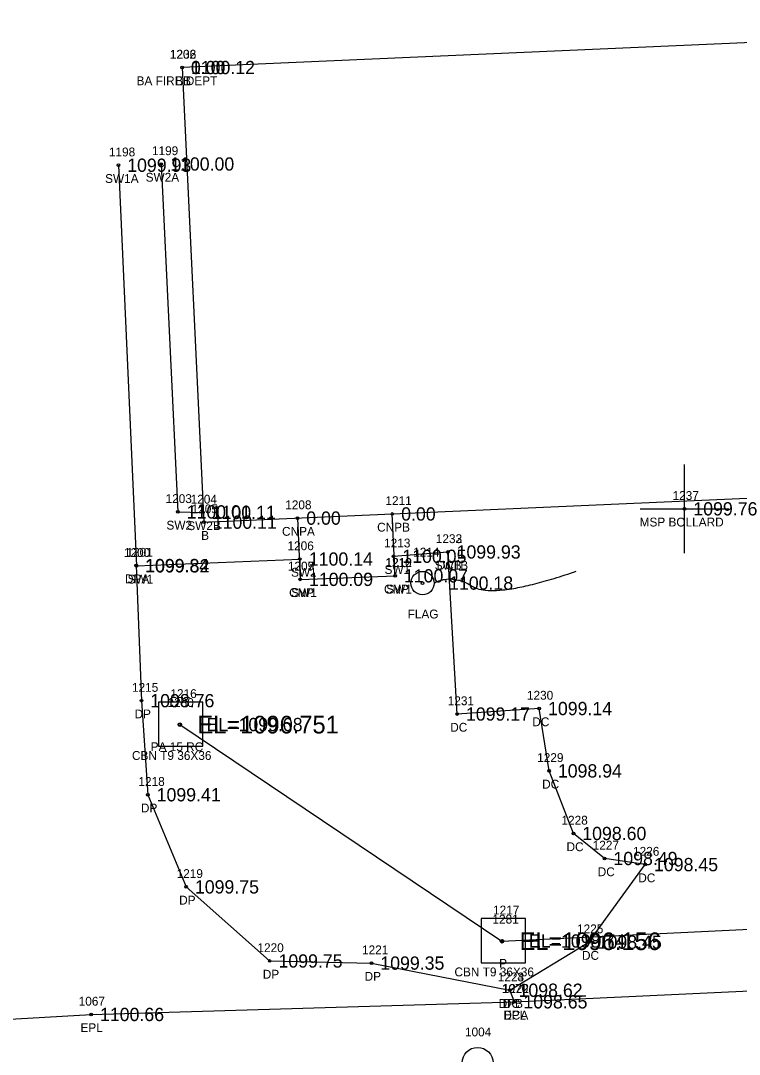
# Model space of a CAD drawing. Extents: x 1539151 to 1541799, y 1198646 to 1201165.
# Drawn here: x 1539498.1 to 1539579.5, y 1199362.1 to 1199479 of the extents above; entities that cross this region are included whole.
import ezdxf

# ---------------------------------------------------------------- set-up
doc = ezdxf.new("R2010")
doc.units = 0
for name, color, linetype in [('RD_EX_Bldg', 7, 'Continuous'), ('RD_EX_Bldg_txCode', 7, 'Continuous'), ('RD_EX_BldgApp', 7, 'Continuous'), ('RD_EX_BldgApp_txCode', 7, 'Continuous'), ('RD_EX_Conc', 7, 'Continuous'), ('RD_EX_Conc_txCode', 7, 'Continuous'), ('RD_EX_DR_Inlet', 7, 'Continuous'), ('RD_EX_DR_Inlet_txCode', 7, 'Continuous'), ('RD_EX_DR_Pipe', 7, 'Continuous'), ('RD_EX_DR_Pipe_txCode', 7, 'Continuous'), ('RD_EX_Driveway', 7, 'Continuous'), ('RD_EX_Driveway_txCode', 7, 'Continuous'), ('RD_EX_DV_Prop_txCode', 7, 'Continuous'), ('RD_EX_DV_PropPin', 7, 'Continuous'), ('RD_EX_Misc', 7, 'Continuous'), ('RD_EX_Misc_txCode', 7, 'Continuous'), ('RD_EX_Road', 7, 'Continuous'), ('RD_EX_Road_txCode', 7, 'Continuous'), ('RD_EX_SU_Telecom', 7, 'Continuous'), ('RD_EX_TX_Bldg_ELEV', 7, 'Continuous'), ('RD_EX_TX_BldgApp_ELEV', 7, 'Continuous'), ('RD_EX_TX_Conc_ELEV', 7, 'Continuous'), ('RD_EX_TX_DR_Inlet_ELEV', 7, 'Continuous'), ('RD_EX_TX_Driveway_ELEV', 7, 'Continuous'), ('RD_EX_TX_Misc_ELEV', 7, 'Continuous'), ('RD_EX_TX_Road_ELEV', 7, 'Continuous'), ('RD_SMD_Locator', 7, 'Continuous'), ('RD_TX_Pipe_ElevEX', 7, 'Continuous')]:
    doc.layers.add(name, color=color, linetype=linetype)

msp = doc.modelspace()

# ---------------------------------------------------------------- linework, layer by layer
at = {"layer": 'RD_EX_Bldg'}
msp.add_lwpolyline([(1539516.41, 1199473.69), (1539518.88, 1199422.27), (1539639.27, 1199427.57), (1539636.8, 1199478.99), (1539516.41, 1199473.69)], dxfattribs=at)
at = {"layer": 'RD_EX_BldgApp'}
msp.add_lwpolyline([(1539529.46, 1199422.73), (1539529.77, 1199415.8), (1539540.51, 1199416.2), (1539540.2, 1199423.2)], dxfattribs=at)
at = {"layer": 'RD_EX_Conc'}
for points in [[(1539509.2, 1199462.64), (1539511.25, 1199417.33), (1539529.75, 1199418.1), (1539529.77, 1199415.8), (1539540.51, 1199416.2), (1539540.33, 1199418.41), (1539546.47, 1199418.9)], [(1539514.06, 1199462.78), (1539515.93, 1199423.43), (1539518.76, 1199423.37)], [(1539554.03, 1199368.02), (1539553.48, 1199369.33), (1539562.44, 1199374.77), (1539568.81, 1199383.54), (1539564.22, 1199384.23), (1539560.69, 1199387.06), (1539557.93, 1199394.14), (1539556.82, 1199401.19), (1539547.53, 1199400.57), (1539546.47, 1199418.9)]]:
    msp.add_lwpolyline(points, dxfattribs=at)
at = {"layer": 'RD_EX_DR_Inlet'}
for p, q in [((1539518.76, 1199396.93), (1539518.76, 1199401.93)), ((1539555.25, 1199372.44), (1539555.25, 1199377.44))]:
    msp.add_line(p, q, dxfattribs=at)
for points in [[(1539518.76, 1199396.93), (1539518.76, 1199401.93), (1539513.76, 1199401.93), (1539513.76, 1199396.93)], [(1539555.25, 1199372.44), (1539555.25, 1199377.44), (1539550.25, 1199377.44), (1539550.25, 1199372.44)]]:
    msp.add_lwpolyline(points, close=True, dxfattribs=at)
at = {"layer": 'RD_EX_DR_Pipe'}
msp.add_lwpolyline([(1539516.15, 1199399.37), (1539552.6, 1199374.87), (1539649.98, 1199379.6)], dxfattribs=at)
at = {"layer": 'RD_EX_Driveway'}
msp.add_lwpolyline([(1539511.22, 1199417.36), (1539511.81, 1199402.08), (1539512.53, 1199391.44), (1539516.86, 1199381.02), (1539526.32, 1199372.64), (1539537.84, 1199372.4), (1539553.48, 1199369.33)], dxfattribs=at)
at = {"layer": 'RD_EX_DV_PropPin'}
msp.add_circle((1539549.85, 1199361.11), 1.75, dxfattribs=at)
at = {"layer": 'RD_EX_Misc'}
for p, q in [((1539573.26, 1199418.78), (1539573.26, 1199428.78)), ((1539568.26, 1199423.78), (1539578.26, 1199423.78))]:
    msp.add_line(p, q, dxfattribs=at)
at = {"layer": 'RD_EX_Road'}
msp.add_lwpolyline([(1539428.76, 1199454.93), (1539416.46, 1199395.23), (1539420.91, 1199377.84), (1539428.29, 1199368.53), (1539440.24, 1199363.06), (1539462.84, 1199364.11), (1539506.12, 1199366.59), (1539554.03, 1199368.02), (1539606.53, 1199370.48), (1539651.89, 1199372.76), (1539672.94, 1199372.91), (1539707.02, 1199374.85), (1539748.7, 1199377.62), (1539769.05, 1199378.19), (1539812.94, 1199380.16), (1539830.48, 1199381.23), (1539857.01, 1199382.87), (1539908.22, 1199385.45), (1539955.82, 1199389.74), (1539996.13, 1199397.4), (1540037.85, 1199410.51), (1540050.26, 1199415.61), (1540093.12, 1199444.78)], dxfattribs=at)
at = {"layer": 'RD_EX_SU_Telecom'}
msp.add_circle((1539543.62, 1199415.38), 1.32, dxfattribs=at)
msp.add_open_spline([(1539544.94, 1199415.38), (1539546.95, 1199416.48), (1539551.63, 1199413.53), (1539561, 1199416.71)], degree=2, dxfattribs=at)
at = {"layer": 'RD_SMD_Locator'}
for centre, radius in [((1539516.41, 1199473.69), 0.15), ((1539516.41, 1199473.69), 0.15), ((1539509.2, 1199462.64), 0.15), ((1539514.06, 1199462.78), 0.15), ((1539515.93, 1199423.43), 0.15), ((1539518.76, 1199423.37), 0.15), ((1539540.2, 1199423.2), 0.15), ((1539573.26, 1199423.78), 0.15), ((1539518.88, 1199422.27), 0.15), ((1539529.46, 1199422.73), 0.15), ((1539540.33, 1199418.41), 0.15), ((1539546.47, 1199418.9), 0.15), ((1539546.47, 1199418.9), 0.15), ((1539511.22, 1199417.36), 0.15), ((1539511.25, 1199417.33), 0.15), ((1539529.75, 1199418.1), 0.15), ((1539540.51, 1199416.2), 0.15), ((1539540.51, 1199416.2), 0.15), ((1539529.77, 1199415.8), 0.15), ((1539529.77, 1199415.8), 0.15), ((1539543.62, 1199415.38), 0.15), ((1539511.81, 1199402.08), 0.15), ((1539556.82, 1199401.19), 0.15), ((1539547.53, 1199400.57), 0.15), ((1539516.15, 1199399.37), 0.2), ((1539516.17, 1199399.38), 0.15), ((1539557.93, 1199394.14), 0.15), ((1539512.53, 1199391.44), 0.15), ((1539560.69, 1199387.06), 0.15), ((1539564.22, 1199384.23), 0.15), ((1539568.81, 1199383.54), 0.15), ((1539516.86, 1199381.02), 0.15), ((1539552.6, 1199374.87), 0.2), ((1539552.66, 1199374.9), 0.15), ((1539562.44, 1199374.77), 0.15), ((1539526.32, 1199372.64), 0.15), ((1539537.84, 1199372.4), 0.15), ((1539553.48, 1199369.33), 0.15), ((1539553.48, 1199369.33), 0.15), ((1539554.03, 1199368.02), 0.15), ((1539554.03, 1199368.02), 0.15), ((1539506.12, 1199366.59), 0.15)]:
    msp.add_circle(centre, radius, dxfattribs=at)

# ---------------------------------------------------------------- texts
at = {"layer": 'RD_EX_Bldg_txCode'}
for s, p in [('1202', (1539515.02, 1199474.69)), ('1236', (1539515.04, 1199474.69)), ('BA FIRE DEPT', (1539511.26, 1199471.69)), ('BB', (1539515.63, 1199471.69)), ('1205', (1539517.49, 1199423.27)), ('B', (1539518.57, 1199420.27))]:
    msp.add_text(s, height=1, dxfattribs=at).set_placement(p)
at = {"layer": 'RD_EX_BldgApp_txCode'}
for s, p in [('1208', (1539528.08, 1199423.73)), ('1211', (1539539.42, 1199424.2)), ('CNPB', (1539538.48, 1199421.2)), ('CNPA', (1539527.72, 1199420.73)), ('1214', (1539542.56, 1199418.38)), ('1209', (1539528.38, 1199416.8)), ('1210', (1539539.41, 1199417.2)), ('CNP', (1539539.26, 1199414.2)), ('CNP', (1539528.52, 1199413.8)), ('FLAG', (1539541.93, 1199411.38))]:
    msp.add_text(s, height=1, dxfattribs=at).set_placement(p)
at = {"layer": 'RD_EX_Conc_txCode'}
for s, p in [('1198', (1539508.13, 1199463.64)), ('1199', (1539513, 1199463.78)), ('SW2A', (1539512.29, 1199460.78)), ('SW1A', (1539507.7, 1199460.64)), ('1203', (1539514.54, 1199424.43)), ('1204', (1539517.38, 1199424.37)), ('SW2', (1539514.64, 1199421.43)), ('SW2B', (1539517, 1199421.37)), ('1232', (1539545.12, 1199419.9)), ('1233', (1539545.12, 1199419.9)), ('1206', (1539528.34, 1199419.1)), ('1213', (1539539.27, 1199419.41)), ('1200', (1539509.83, 1199418.33)), ('1207', (1539528.38, 1199416.8)), ('SW1', (1539539.32, 1199416.41)), ('1212', (1539539.45, 1199417.2)), ('SW1B', (1539544.99, 1199416.9)), ('DCB', (1539545.22, 1199416.9)), ('SW1', (1539510.25, 1199415.33)), ('SW1', (1539528.74, 1199416.1)), ('SW1', (1539539.51, 1199414.2)), ('SW1', (1539528.76, 1199413.8)), ('1231', (1539546.47, 1199401.57)), ('1230', (1539555.43, 1199402.19)), ('DC', (1539556.04, 1199399.19)), ('DC', (1539546.75, 1199398.57)), ('1229', (1539556.59, 1199395.14)), ('DC', (1539557.15, 1199392.14)), ('1228', (1539559.34, 1199388.06)), ('DC', (1539559.91, 1199385.06)), ('1227', (1539562.87, 1199385.23)), ('1226', (1539567.44, 1199384.54)), ('DC', (1539563.44, 1199382.23)), ('DC', (1539568.03, 1199381.54)), ('1225', (1539561.1, 1199375.77)), ('DC', (1539561.66, 1199372.77)), ('1223', (1539552.13, 1199370.33)), ('1222', (1539552.68, 1199369.02)), ('DC', (1539552.7, 1199367.33)), ('DCA', (1539552.76, 1199366.02))]:
    msp.add_text(s, height=1, dxfattribs=at).set_placement(p)
at = {"layer": 'RD_EX_DR_Inlet_txCode'}
for s, p in [('1216', (1539515.09, 1199402.38)), ('CBN T9 36X36', (1539510.74, 1199395.38)), ('1217', (1539551.6, 1199377.9)), ('CBN T9 36X36', (1539547.23, 1199370.9))]:
    msp.add_text(s, height=1, dxfattribs=at).set_placement(p)
at = {"layer": 'RD_EX_DR_Pipe_txCode'}
for s, p in [('1280', (1539514.76, 1199401.37)), ('PA 15 RC', (1539512.86, 1199396.37)), ('1281', (1539551.53, 1199376.87)), ('P', (1539552.29, 1199371.87))]:
    msp.add_text(s, height=1, dxfattribs=at).set_placement(p)
at = {"layer": 'RD_EX_Driveway_txCode'}
for s, p in [('1201', (1539510.12, 1199418.36)), ('DPA', (1539509.95, 1199415.36)), ('1215', (1539510.74, 1199403.08)), ('DP', (1539511.03, 1199400.08)), ('1218', (1539511.47, 1199392.44)), ('DP', (1539511.75, 1199389.44)), ('1219', (1539515.79, 1199382.02)), ('DP', (1539516.08, 1199379.02)), ('1220', (1539524.94, 1199373.64)), ('1221', (1539536.77, 1199373.4)), ('DP', (1539525.54, 1199370.64)), ('DP', (1539537.06, 1199370.4)), ('1224', (1539552.13, 1199370.33)), ('DPB', (1539552.23, 1199367.33))]:
    msp.add_text(s, height=1, dxfattribs=at).set_placement(p)
at = {"layer": 'RD_EX_DV_Prop_txCode'}
msp.add_text('1004', height=1, dxfattribs=at).set_placement((1539548.42, 1199364.11))
at = {"layer": 'RD_EX_Misc_txCode'}
for s, p in [('1237', (1539571.91, 1199424.78)), ('MSP BOLLARD', (1539568.18, 1199421.78))]:
    msp.add_text(s, height=1, dxfattribs=at).set_placement(p)
at = {"layer": 'RD_EX_Road_txCode'}
for s, p in [('1070', (1539552.6, 1199369.02)), ('1067', (1539504.71, 1199367.59)), ('EPL', (1539552.82, 1199366.02)), ('EPL', (1539504.91, 1199364.59))]:
    msp.add_text(s, height=1, dxfattribs=at).set_placement(p)
at = {"layer": 'RD_EX_TX_Bldg_ELEV'}
for s, p in [('0.00', (1539517.41, 1199472.94)), ('1100.12', (1539517.41, 1199472.94)), ('1100.11', (1539519.88, 1199421.52))]:
    msp.add_text(s, height=1.5, dxfattribs=at).set_placement(p)
at = {"layer": 'RD_EX_TX_BldgApp_ELEV'}
for s, p in [('0.00', (1539530.46, 1199421.98)), ('0.00', (1539541.2, 1199422.45)), ('1100.09', (1539530.77, 1199415.05)), ('1100.07', (1539541.51, 1199415.45)), ('1100.18', (1539546.62, 1199414.63))]:
    msp.add_text(s, height=1.5, dxfattribs=at).set_placement(p)
at = {"layer": 'RD_EX_TX_Conc_ELEV'}
for s, p in [('1099.93', (1539510.2, 1199461.89)), ('1100.00', (1539515.06, 1199462.03)), ('1100.01', (1539516.93, 1199422.68)), ('1100.11', (1539519.76, 1199422.62)), ('1100.14', (1539530.75, 1199417.35)), ('1100.05', (1539541.33, 1199417.66)), ('1099.93', (1539547.47, 1199418.15)), ('1099.93', (1539547.47, 1199418.15)), ('1099.82', (1539512.25, 1199416.58)), ('1100.09', (1539530.77, 1199415.05)), ('1100.07', (1539541.51, 1199415.45)), ('1099.17', (1539548.53, 1199399.82)), ('1099.14', (1539557.82, 1199400.44)), ('1098.94', (1539558.93, 1199393.39)), ('1098.60', (1539561.69, 1199386.31)), ('1098.49', (1539565.22, 1199383.48)), ('1098.45', (1539569.81, 1199382.79)), ('1098.45', (1539563.44, 1199374.02)), ('1098.62', (1539554.48, 1199368.58)), ('1098.65', (1539555.03, 1199367.27))]:
    msp.add_text(s, height=1.5, dxfattribs=at).set_placement(p)
at = {"layer": 'RD_EX_TX_DR_Inlet_ELEV'}
for s, p in [('EL=1099.08', (1539519.17, 1199398.63)), ('EL=1098.74', (1539555.66, 1199374.15))]:
    msp.add_text(s, height=1.5, dxfattribs=at).set_placement(p)
at = {"layer": 'RD_EX_TX_Driveway_ELEV'}
for s, p in [('1099.84', (1539512.22, 1199416.61)), ('1098.76', (1539512.81, 1199401.33)), ('1099.41', (1539513.53, 1199390.69)), ('1099.75', (1539517.86, 1199380.27)), ('1099.75', (1539527.32, 1199371.89)), ('1099.35', (1539538.84, 1199371.65)), ('1098.62', (1539554.48, 1199368.58))]:
    msp.add_text(s, height=1.5, dxfattribs=at).set_placement(p)
at = {"layer": 'RD_EX_TX_Misc_ELEV'}
msp.add_text('1099.76', height=1.5, dxfattribs=at).set_placement((1539574.26, 1199423.03))
at = {"layer": 'RD_EX_TX_Road_ELEV'}
for s, p in [('1098.65', (1539555.03, 1199367.27)), ('1100.66', (1539507.12, 1199365.84))]:
    msp.add_text(s, height=1.5, dxfattribs=at).set_placement(p)
at = {"layer": 'RD_TX_Pipe_ElevEX'}
for s, p in [('EL=1096.751', (1539518.15, 1199398.37)), ('EL=1096.156', (1539554.6, 1199373.87))]:
    msp.add_text(s, height=2, dxfattribs=at).set_placement(p)

doc.saveas('drawing.dxf')
